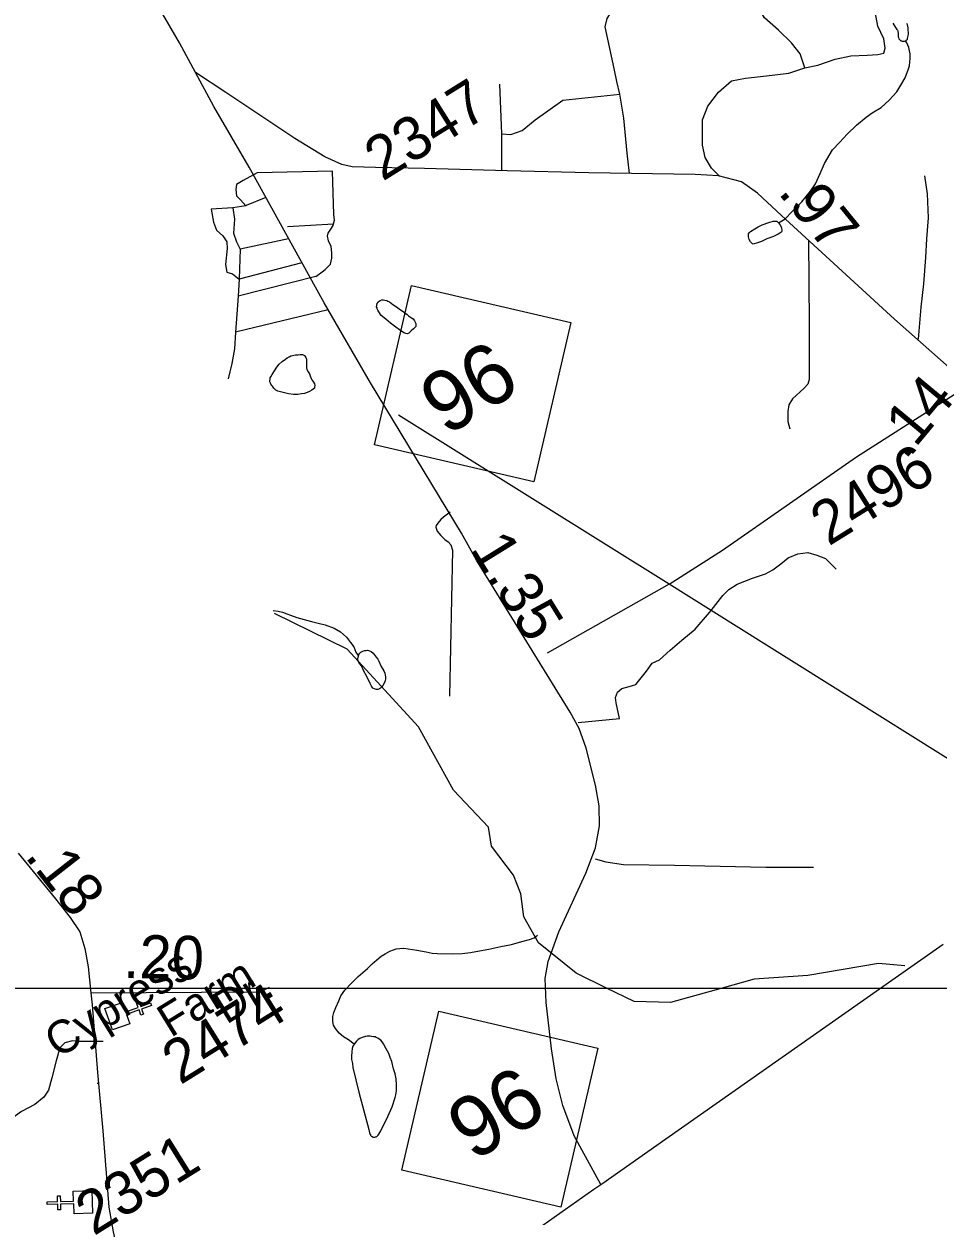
# Model space of a CAD drawing. Extents: x 2001466 to 31450019, y -30647475 to 847247.
# Drawn here: x 2204779 to 2210046, y 744293 to 751164 of the extents above; entities that cross this region are included whole.
import ezdxf

# ---------------------------------------------------------------- set-up
doc = ezdxf.new("R2010")
doc.units = 0
for name, color, linetype in [('Exist Boundary Political CountyLine', 7, 'Continuous'), ('Exist Cultural Church CELL', 7, 'Continuous'), ('Exist Hydrographic Creek Single Shore', 7, 'Continuous'), ('Exist Hydrographic Misc Water Feature', 7, 'Continuous'), ('Exist Road Non-System Type 51', 7, 'Continuous'), ('Exist Road Non-System Type 51 Label', 7, 'Continuous'), ('Exist Road Primary NC Attributed', 7, 'Continuous'), ('Exist Road Primary NC Service Mileage Hundredths English Label', 7, 'Continuous'), ('Exist Road Primary NC Shield CELL', 7, 'Continuous'), ('Exist Road Primary NC Shield Number Label', 7, 'Continuous'), ('Exist Road Secondary Mileage Hundredths English Label', 7, 'Continuous'), ('Exist Road Secondary Type 51 Attributed', 7, 'Continuous'), ('Exist Road Secondary Type 51 Label', 7, 'Continuous'), ('Exist Road Secondary Type 51 Number Label', 7, 'Continuous'), ('Exist Utilities Electrical Transmission Line', 7, 'Continuous'), ('Map Preparation Inset Cut Line', 7, 'Continuous')]:
    doc.layers.add(name, color=color, linetype=linetype)

msp = doc.modelspace()

# ---------------------------------------------------------------- linework, layer by layer
at = {"layer": 'Exist Boundary Political CountyLine'}
msp.add_lwpolyline([(2207605.3, 744126.8), (2208063.6, 744447.8), (2208103.1, 744475.5), (2208113.8, 744483.1), (2208477.8, 744738), (2209797.9, 745665.9), (2210074.9, 745860.5)], dxfattribs=at)
at = {"layer": 'Exist Cultural Church CELL'}
for points in [[(2205346.5, 745524.9), (2205365.5, 745471.2), (2205437.3, 745496.4), (2205426.8, 745526.6), (2205441.8, 745531.9), (2205452.4, 745501.7), (2205509.2, 745521.6), (2205514.5, 745506.5), (2205457.7, 745486.6), (2205468.3, 745456.4), (2205453.2, 745451.1), (2205442.6, 745481.3), (2205370.8, 745456.1), (2205389.8, 745401.7), (2205289.3, 745366.4), (2205246.1, 745489.7)], [(2205068, 744307.2), (2205066.1, 744364.1), (2204990, 744361.8), (2204991, 744329.8), (2204975, 744329.3), (2204974, 744361.3), (2204913.9, 744359.5), (2204913.5, 744375.5), (2204973.6, 744377.3), (2204972.6, 744409.3), (2204988.6, 744409.8), (2204989.5, 744377.8), (2205065.6, 744380.1), (2205064, 744437.8), (2205170.4, 744441), (2205174.4, 744310.4)]]:
    msp.add_lwpolyline(points, close=True, dxfattribs=at)
at = {"layer": 'Exist Hydrographic Creek Single Shore'}
for points in [[(2207743.7, 745868.8), (2207659.8, 746018.1), (2207641.8, 746149.7), (2207599.8, 746258.8), (2207473.6, 746425.4), (2207455.8, 746534), (2207254.6, 746748.1), (2207052.7, 747113.1), (2206640.7, 747561), (2206222.8, 747766.4)], [(2208136.1, 745607.9), (2207961.7, 745693.7), (2207743.7, 745868.8)], [(2209855, 745735.1), (2209702.8, 745749.9), (2209294.7, 745679.5), (2208986.7, 745659.7), (2208801.3, 745607.9)], [(2208801.3, 745607.9), (2208504.6, 745525.2), (2208295.7, 745529.4), (2208136.1, 745607.9)]]:
    msp.add_lwpolyline(points, dxfattribs=at)
at = {"layer": 'Exist Hydrographic Misc Water Feature'}
for points in [[(2209785, 751167.7), (2209801, 751143.8), (2209809.2, 751132), (2209811.2, 751128), (2209813.5, 751124), (2209813.3, 751120), (2209815.3, 751110), (2209815.5, 751098.2), (2209815.5, 751090.1), (2209817.8, 751086.1), (2209819.9, 751078), (2209824, 751074.2), (2209827.8, 751069.9), (2209831.9, 751066.1), (2209835.8, 751066.3), (2209839.5, 751064.1), (2209845.5, 751064.1), (2209852, 751064.3), (2209857.8, 751066.3)], [(2209857.8, 751066.3), (2209861.7, 751068.5), (2209863.5, 751072.3), (2209869.3, 751076.3), (2209869.5, 751080.3), (2209873.6, 751094.3), (2209875.6, 751106.6), (2209875, 751116.3), (2209873, 751124.4), (2209873.2, 751140.2), (2209870.9, 751150.2), (2209868.9, 751158.3), (2209866.8, 751166.3)], [(2209127, 750017.7), (2209165.1, 750039.9), (2209204.9, 750082.2), (2209260.1, 750138.3), (2209311.7, 750200.7), (2209339.2, 750241.2), (2209367.1, 750301.1), (2209390.9, 750359.1), (2209438.2, 750437.6), (2209479.7, 750482), (2209521.3, 750528), (2209575, 750580.4), (2209630.8, 750626.7), (2209666.9, 750651.3), (2209718.6, 750681.6), (2209764.3, 750723.8), (2209807.5, 750772), (2209831.3, 750810.2), (2209857, 750852.2), (2209874.8, 750904.7), (2209880.5, 750922.4), (2209882.6, 750944.5), (2209884.2, 750964.5), (2209884.2, 750990.4), (2209881.8, 751008.6), (2209877.9, 751028.3), (2209865.6, 751054.5), (2209857.8, 751066.3)], [(2209127, 750017.7), (2209133.3, 750007.8), (2209141.3, 749993.6), (2209143.6, 749983.9), (2209145.4, 749977.6), (2209145.2, 749971.9), (2209143.4, 749965.7), (2209139.3, 749961.8), (2209133.5, 749957.8), (2209123.7, 749951.6), (2209097.9, 749939.3), (2209059.7, 749925.2), (2209027.7, 749908.9), (2209000.1, 749900.9), (2208985.7, 749896.6), (2208980, 749894.7), (2208975.9, 749896.5), (2208972, 749900.7), (2208966, 749908.5), (2208957.8, 749920.7), (2208955.8, 749928.7), (2208953.7, 749936.4), (2208953.7, 749946.5), (2208953.7, 749954.6), (2208957.6, 749960.5), (2208965.6, 749966.6), (2208989.4, 749982.9), (2209009.3, 749994.9), (2209033.1, 750005.1), (2209071.2, 750019.2), (2209095, 750027.4), (2209107.3, 750027.5), (2209113.2, 750027.5), (2209117.1, 750027.7), (2209123.3, 750021.5), (2209127, 750017.7)], [(2206949.3, 749516.6), (2206969.6, 749503), (2206987.7, 749488.9), (2206995.7, 749481.2), (2207012.1, 749469), (2207021.7, 749463.5), (2207030.1, 749453.3), (2207034, 749445.4), (2207038.1, 749437.5), (2207038.1, 749431.4), (2207037.9, 749423.3), (2207038.1, 749419.6), (2207024.2, 749407.1), (2207010.4, 749395.4), (2207002.2, 749387.3), (2206996.5, 749381.3), (2206992.8, 749379), (2206988.7, 749377.2), (2206980.5, 749378.9), (2206974.3, 749381), (2206968.8, 749383.1), (2206942.4, 749400.8), (2206922.1, 749416.9), (2206892.1, 749438.5), (2206864.2, 749462.1), (2206837.8, 749484), (2206824, 749503.9), (2206817.5, 749513.8), (2206815.4, 749521.8), (2206813.6, 749527.8), (2206811.5, 749533.8), (2206813.2, 749543.6), (2206815.4, 749551.8), (2206819.3, 749559.8), (2206825.3, 749565.7), (2206831.2, 749569.7), (2206841.3, 749573.9), (2206851.3, 749574), (2206859.1, 749572), (2206869.4, 749570), (2206875.1, 749566.4), (2206885.1, 749562.4), (2206905.4, 749546.4), (2206925.5, 749532.4), (2206949.3, 749516.6)], [(2206416, 749159.5), (2206424.2, 749147.3), (2206428.3, 749135.3), (2206434.4, 749119.4), (2206438.5, 749113.5), (2206444.5, 749105.3), (2206448.6, 749099.4), (2206452.9, 749089.4), (2206454.5, 749079.4), (2206452.9, 749071.6), (2206452.7, 749065.5), (2206446.5, 749059.5), (2206437.1, 749053.3), (2206425, 749045.3), (2206410.9, 749039.4), (2206395.1, 749033.2), (2206379.1, 749031.2), (2206356.9, 749028.9), (2206333.1, 749028.8), (2206303.2, 749032.5), (2206281.1, 749038.3), (2206257.1, 749044.3), (2206242.9, 749048.1), (2206231, 749053.9), (2206219.1, 749063.9), (2206210.9, 749075.7), (2206206.8, 749079.9), (2206202.7, 749087.9), (2206199, 749093.7), (2206197, 749101.7), (2206196.6, 749107.8), (2206198.4, 749115.6), (2206198.4, 749123.8), (2206202.5, 749129.6), (2206210.3, 749143.9), (2206222.2, 749164), (2206236, 749185.8), (2206250.1, 749202), (2206267.7, 749218), (2206285.8, 749232.3), (2206295.8, 749238.5), (2206307.7, 749244.4), (2206317.8, 749250.6), (2206327.4, 749252.8), (2206343.4, 749256.8), (2206359.6, 749256.8), (2206371.3, 749258.7), (2206383.8, 749258.9), (2206391.6, 749254.8), (2206395.5, 749253), (2206403.3, 749241.3), (2206405.7, 749237.3), (2206407.8, 749227.2), (2206408.2, 749201.2), (2206407.8, 749181.4), (2206410, 749171.3), (2206416, 749159.5)], [(2206215.6, 747782.6), (2206243.5, 747778.8), (2206269.8, 747772.8), (2206294, 747765), (2206315.5, 747756.9), (2206352, 747743.3), (2206394.3, 747731.6), (2206436.1, 747720.1), (2206474.4, 747710.2), (2206514, 747700.6), (2206566.5, 747680.9), (2206602.6, 747661.2), (2206638.7, 747629.4), (2206660.8, 747599.3), (2206679.1, 747573.5), (2206691, 747543.6), (2206707, 747519.7)], [(2206846.8, 747351), (2206838.8, 747340.8), (2206834.3, 747335), (2206828.6, 747331), (2206818.9, 747328.8), (2206808.7, 747328.7), (2206798.2, 747332.7), (2206790.4, 747336.4), (2206782.2, 747346.5), (2206774.4, 747362.3), (2206754.1, 747402.2), (2206737.7, 747433.9), (2206723.8, 747464.1), (2206709.6, 747483.6), (2206705.3, 747492), (2206703.5, 747504), (2206705.7, 747513.8), (2206707, 747519.7)], [(2206707, 747519.7), (2206709.2, 747529.9), (2206715.2, 747538), (2206721.3, 747543.9), (2206731.4, 747548.1), (2206740.8, 747551.9), (2206751, 747552), (2206759, 747554), (2206765.2, 747552.3), (2206770.7, 747550.2), (2206779.5, 747546.5), (2206791.4, 747536.6), (2206809.5, 747514.4), (2206817.7, 747502.6), (2206823.4, 747490.8), (2206838, 747461), (2206851.9, 747435), (2206857.9, 747423.1), (2206859.7, 747411.1), (2206862, 747399), (2206862.2, 747389.2), (2206860.3, 747378.9), (2206858.1, 747373.2), (2206846.8, 747351)], [(2206682.6, 745284.7), (2206648.5, 745310.1), (2206620.6, 745326.1), (2206594.6, 745347.9), (2206574.1, 745373.7), (2206563.8, 745393.9), (2206559.9, 745415.5), (2206559.9, 745443.5), (2206565.7, 745465.8), (2206577, 745495.7), (2206592.7, 745533.9), (2206605, 745563.7), (2206629, 745596.2), (2206664.3, 745634.3), (2206705.9, 745674.6), (2206757.8, 745720.8), (2206785.5, 745747), (2206813.4, 745771.1), (2206837.2, 745791.5), (2206861.2, 745805.7), (2206886.8, 745819.7), (2206908.9, 745827.7), (2206923.3, 745834), (2206944.8, 745836.1), (2206969, 745838.1), (2206993, 745834.5), (2207043, 745826.9), (2207096.8, 745817.2), (2207131.2, 745809.5), (2207160.9, 745807.5), (2207248.9, 745804.4), (2207303.2, 745806.7), (2207352.7, 745813), (2207404.7, 745821.4), (2207458.7, 745831.9), (2207526.5, 745846.4), (2207588.5, 745858.5), (2207648.1, 745875.1), (2207692.4, 745887.5), (2207718.3, 745897.4), (2207738.2, 745911.8)], [(2206682.6, 745284.7), (2206674.6, 745272.5), (2206671.1, 745258.4), (2206668.8, 745240.5), (2206667, 745214.4), (2206667.4, 745196.5), (2206671.5, 745172.3), (2206673.9, 745150.5), (2206709, 745006.9), (2206766, 744793.4), (2206770.3, 744773.3), (2206772, 744767.4), (2206774.2, 744763.4), (2206778.3, 744757.5), (2206780.8, 744753.5), (2206784.7, 744751.6), (2206790.4, 744747.5), (2206798.4, 744747.5), (2206804.8, 744749.4), (2206808.5, 744749.7), (2206812.8, 744751.5), (2206816.5, 744755.8), (2206819.9, 744759.7), (2206824.4, 744765.5), (2206836.1, 744785.6), (2206875.5, 744868.1), (2206900.9, 744922.3), (2206919, 744976.4), (2206922.5, 744992.5), (2206926.4, 745016.2), (2206926.4, 745048.3), (2206923.7, 745084.4), (2206917.7, 745114.1), (2206909.5, 745142.1), (2206899.5, 745184.1), (2206889, 745208), (2206880.8, 745230), (2206866.9, 745258.1), (2206850.7, 745285.6), (2206842.5, 745297.8), (2206834.7, 745307.5), (2206826.3, 745313.7), (2206818.3, 745319.3), (2206808.5, 745323.3), (2206802.3, 745327.4), (2206792.5, 745327.3), (2206782.2, 745329.3), (2206774.4, 745331.2), (2206764.6, 745331.1), (2206756.6, 745331.1), (2206746.5, 745329), (2206728.5, 745322.7), (2206714.7, 745316.8), (2206704.3, 745310.6), (2206694.7, 745300.7), (2206682.6, 745284.7)]]:
    msp.add_lwpolyline(points, dxfattribs=at)
at = {"layer": 'Exist Road Non-System Type 51'}
for p, q in [((2207531.7, 750531), (2207520.3, 750815.9)), ((2207531.7, 750322.2), (2207531.7, 750531)), ((2206058.2, 750116.1), (2205983.8, 750103.1)), ((2206298.4, 749995.8), (2206563.8, 750012.1)), ((2206304.2, 749925.1), (2206026.1, 749866.1)), ((2206026.1, 749866.1), (2206018.6, 749692.3)), ((2206380.4, 749787.4), (2206018.6, 749692.3)), ((2206460.8, 749707.2), (2206014.6, 749594.4)), ((2206018.6, 749692.3), (2206014.6, 749594.4)), ((2206014.6, 749594.4), (2205998.3, 749386.7)), ((2206531.4, 749516.4), (2205998.3, 749386.7))]:
    msp.add_line(p, q, dxfattribs=at)
for points in [[(2208212.8, 750759.1), (2208195.9, 750831.1), (2208180.7, 750907), (2208127.6, 751146.3), (2208138.9, 751195.6), (2208165.5, 751237.4), (2208199.7, 751237.4), (2208271.8, 751233.6), (2208336.3, 751245), (2208393.2, 751298.2), (2208480.5, 751408.3), (2208556.5, 751491.9), (2208590.6, 751529.8), (2208598.2, 751628.6), (2208602, 751742.5), (2208613.4, 751799.5), (2208643.8, 751833.6), (2208719.7, 751890.6), (2208772.8, 751909.6), (2208829.7, 751921), (2208920.8, 751985.6)], [(2209277.6, 750910.8), (2209353.5, 750926), (2209452.2, 750960.2), (2209543.3, 750979.2), (2209638.2, 750983), (2209698.9, 750986.8), (2209733.1, 750994.4), (2209740.7, 751024.7), (2209733.1, 751077.9), (2209698.9, 751150.1), (2209683.7, 751233.6), (2209645.8, 751427.3), (2209626.8, 751533.6), (2209619.2, 751621)], [(2209277.6, 750910.8), (2209251, 750990.6), (2209201.7, 751055.1), (2209125.8, 751127.3), (2209046.1, 751199.4), (2209000.5, 751275.4), (2208977.8, 751362.7), (2208985.4, 751472.9)], [(2208786.6, 750287), (2208740.3, 750331.9), (2208703.9, 750392.9), (2208687.8, 750464.7), (2208687.8, 750526), (2208689.5, 750611.6), (2208719.7, 750690.6), (2208780.4, 750770.3), (2208856.3, 750834.9), (2208936, 750850.1), (2209057.5, 750865.2), (2209186.5, 750880.4), (2209277.6, 750910.8)], [(2207531.7, 750531), (2207584.8, 750527.3), (2207649.3, 750550), (2207725.2, 750610.8), (2207884.6, 750724.7), (2208212.8, 750759.1)], [(2208268.4, 750301.8), (2208255.4, 750418.8), (2208234.9, 750620.2), (2208212.8, 750759.1)], [(2206123.2, 750306), (2206043.2, 750261.4), (2206003.6, 750238.3), (2206000.3, 750208.7), (2206003.6, 750172.4), (2206026.7, 750149.3), (2206058.2, 750116.1)], [(2206563.8, 750012.1), (2206569.5, 750032.9), (2206564.1, 750065), (2206557.3, 750315.1), (2206123.2, 750306)], [(2209968, 750289.1), (2209983.9, 750184.8), (2209989, 750046.7), (2209978.5, 749925), (2209974.3, 749817.1), (2209961.2, 749665.4), (2209946.4, 749531.7), (2209930.5, 749346.2)], [(2205983.8, 750103.1), (2205858.6, 750096.6), (2205871.8, 750020.7), (2205888.3, 749974.5), (2205924.5, 749941.6), (2205947.6, 749908.6), (2205950.9, 749869), (2205941, 749776.7), (2205947.6, 749733.8), (2205980.6, 749723.9), (2206018.6, 749692.3)], [(2205983.8, 750103.1), (2205991.7, 750038.8), (2205987.1, 749958.1), (2206003.6, 749908.6), (2206026.1, 749866.1)], [(2206172.7, 750162.8), (2206059.6, 750116.3), (2206058.2, 750116.1)], [(2206460.8, 749707.2), (2206497.3, 749734.4), (2206515.6, 749748.1), (2206546.2, 749779.4), (2206552.9, 749813.3), (2206553.6, 749845.3), (2206550.3, 749881.3), (2206535, 749913.6), (2206527.5, 749939.8), (2206531.9, 749957.7), (2206548.4, 749981.3), (2206560.8, 750001.1), (2206563.8, 750012.1)], [(2209300.1, 749916.8), (2209303.7, 749434.5), (2209302.7, 749114.5), (2209295.1, 749088), (2209274.2, 749065.2), (2209207.8, 749002.5), (2209186.9, 748968.3), (2209181.2, 748930.4), (2209181.2, 748873.4), (2209192.6, 748829.7)], [(2205998.3, 749386.7), (2205992.3, 749290.9), (2205976.6, 749207.2), (2205956.8, 749117.6)], [(2207234.7, 748349.6), (2207196.1, 748320.4), (2207181.9, 748308.6), (2207163.4, 748287), (2207155.2, 748273.2), (2207153, 748263.3), (2207160.5, 748241.1), (2207182, 748214.7), (2207203.5, 748192.2), (2207223.2, 748179.8), (2207238.9, 748161.5), (2207248.2, 748131.3), (2207230.9, 747289.8)], [(2208738.1, 747782.6), (2208805.5, 747870.3), (2208839.7, 747904.5), (2208889, 747934.9), (2208976.3, 747969.1), (2209052.3, 747995.6), (2209094, 748018.4), (2209139.6, 748052.6), (2209181.3, 748086.8), (2209238.2, 748109.6), (2209295.2, 748117.2), (2209348.3, 748102), (2209397.7, 748083), (2209458.4, 748022.2)], [(2207973.2, 747137.5), (2208209.6, 747160.1), (2208190.7, 747251.3), (2208186.9, 747281.7), (2208198.3, 747312.1), (2208224.8, 747334.8), (2208266.6, 747346.2), (2208304.5, 747357.6), (2208365.3, 747433.6), (2208399.4, 747479.2), (2208441.2, 747498.1), (2208501.9, 747555.1), (2208570.2, 747612.1), (2208646.1, 747676.6), (2208729.6, 747771.6), (2208738.1, 747782.6)], [(2208070.3, 746351.8), (2208131.8, 746334.2), (2208234.3, 746319), (2208526.6, 746315.2), (2209054.2, 746303.8), (2209327.4, 746303.8)], [(2205236.8, 745300.2), (2205092.5, 745300.1), (2205058.6, 745302.8), (2205014.3, 745291.7), (2204985.7, 745262.3), (2204964.2, 745188.7), (2204940.2, 745091.2), (2204920.8, 745019.7), (2204893.9, 744978.2), (2204843.1, 744937.3), (2204766.3, 744896.8), (2204689.1, 744840.4), (2204632.1, 744791.6), (2204565.2, 744743), (2204502.5, 744712.3), (2204401.5, 744660.4), (2204356.9, 744629.3), (2204320.2, 744596.1), (2204287.2, 744548.7), (2204250.6, 744515.5), (2204195.7, 744474.6), (2204116.7, 744426.3), (2204063.9, 744382.1)]]:
    msp.add_lwpolyline(points, dxfattribs=at)
at = {"layer": 'Exist Road Non-System Type 51 Label'}
msp.add_line((2205201.1, 745058.8), (2205204.4, 745058.9), dxfattribs=at)
at = {"layer": 'Exist Road Primary NC Attributed'}
for points in [[(2205767.9, 750883), (2205676.3, 751054.8), (2205566.5, 751243.3), (2205434.1, 751502.9), (2205238.9, 751861.1), (2205150, 752049.5), (2205122.8, 752097.7), (2205020.8, 752254.8)], [(2208103.1, 744475.5), (2207949.1, 744756.3), (2207884.2, 744930.1), (2207846.5, 745085.1), (2207819.3, 745256.8), (2207789, 745524.9), (2207782.7, 745663.1), (2207799.4, 745761.5), (2207860.1, 745931.2), (2208016.1, 746270.4), (2208072.6, 746415), (2208095.6, 746542.7), (2208093.5, 746657.9), (2208072.6, 746777.3), (2208019.2, 746990.9), (2207977.3, 747104), (2207927.1, 747198.2), (2207386.1, 748073.6), (2207300.3, 748228.6), (2206776.1, 749095.6), (2206508.2, 749556.3), (2206076.1, 750337.5), (2205873.1, 750687.2), (2205767.9, 750883)]]:
    msp.add_lwpolyline(points, dxfattribs=at)
at = {"layer": 'Exist Road Primary NC Shield CELL'}
for points in [[(2206798.9, 748737.9), (2207012.1, 749655.3), (2207929.5, 749442.2), (2207716.3, 748524.7)], [(2206955.8, 744557.8), (2207169, 745475.2), (2208086.4, 745262), (2207873.2, 744344.6)]]:
    msp.add_lwpolyline(points, close=True, dxfattribs=at)
at = {"layer": 'Exist Road Secondary Type 51 Attributed'}
for points in [[(2210278.2, 749039.6), (2210143.1, 749155.3), (2209795.7, 749463.1), (2209143.8, 750060), (2209005.7, 750187.8), (2208913.6, 750252.7), (2208781.7, 750288.3), (2208645.7, 750296.7), (2208033.6, 750305), (2207562.7, 750317.6), (2207086.6, 750330.2), (2206805.1, 750335.4), (2206670.1, 750340.6), (2206610.5, 750353.2), (2206513.7, 750398.2), (2206340, 750502.9), (2205942.4, 750768.9), (2205767.9, 750883)], [(2204745.4, 746384.7), (2204961.5, 746121.9), (2205045.2, 746014.8), (2205100.8, 745930.7), (2205130.9, 745835.5), (2205149.2, 745729.1), (2205165.6, 745580.3)], [(2205165.6, 745580.3), (2206120.7, 745586.5), (2206140.5, 745591.1), (2206158.7, 745595.7), (2206193.8, 745612.4)], [(2205165.6, 745580.3), (2205173.3, 745511.3), (2205204.1, 745120.7), (2205233.4, 744785.6), (2205268.5, 744344.8), (2205293.6, 744202.4), (2205383.6, 743785.6), (2205455.8, 743530.1), (2205543.7, 743314.4), (2205667.2, 743084), (2205800.4, 742874.8)]]:
    msp.add_lwpolyline(points, dxfattribs=at)
at = {"layer": 'Exist Utilities Electrical Transmission Line'}
for p, q in [((2208496, 747935.8), (2206938.3, 748909.5)), ((2208496, 747935.8), (2207793.9, 747538.2)), ((2208738.1, 747782.6), (2208496, 747935.8))]:
    msp.add_line(p, q, dxfattribs=at)
for points in [[(2208496, 747935.8), (2208803.9, 748131.4), (2209576.8, 748669.4), (2210228.3, 749086)], [(2210897.5, 746439), (2210872.9, 746446.1), (2208738.1, 747782.6)]]:
    msp.add_lwpolyline(points, dxfattribs=at)
at = {"layer": 'Map Preparation Inset Cut Line'}
for p, q in [((2202091.1, 745607.9), (2205205.2, 745607.9)), ((2205205.2, 745607.9), (2207796.6, 745607.9)), ((2207796.6, 745607.9), (2208136.1, 745607.9)), ((2208136.1, 745607.9), (2208801.3, 745607.9)), ((2208801.3, 745607.9), (2209730.1, 745607.9))]:
    msp.add_line(p, q, dxfattribs=at)
msp.add_lwpolyline([(2209730.1, 745607.9), (2211302.1, 745607.9), (2211302.1, 746701.8)], dxfattribs=at)

# ---------------------------------------------------------------- texts
at = {"layer": 'Exist Road Primary NC Service Mileage Hundredths English Label'}
msp.add_text('1.35', height=250, rotation=301.71539, dxfattribs=at).set_placement((2207345.7, 748139))
at = {"layer": 'Exist Road Primary NC Shield Number Label'}
for p in [(2207211.4, 748783.5), (2207368.4, 744603.4)]:
    msp.add_text('96', height=350, rotation=31.91803, dxfattribs=at).set_placement(p)
at = {"layer": 'Exist Road Secondary Mileage Hundredths English Label'}
for s, rotation, p in [('.97', 309.17025, (2209119.4, 750190.7)), ('.14', 50.24174, (2209855.6, 748646.7)), ('.18', 308.00448, (2204779.9, 746366.2)), ('.20', 358.80785, (2205349.7, 745665.8))]:
    msp.add_text(s, height=250, rotation=rotation, dxfattribs=at).set_placement(p)
at = {"layer": 'Exist Road Secondary Type 51 Label'}
for s, p in [('Cypress ', (2204975.7, 745199.1)), ('Farm', (2205625.1, 745319.2)), ('Dr.', (2205945.7, 745395.1))]:
    msp.add_text(s, height=190, rotation=31.65519, dxfattribs=at).set_placement(p)
at = {"layer": 'Exist Road Secondary Type 51 Number Label'}
for s, p in [('2347', (2206845.1, 750253.5)), ('2496', (2209415.2, 748151.3)), ('2474', (2205679.8, 745046.6)), ('2351', (2205181.4, 744176.3))]:
    msp.add_text(s, height=250, rotation=31.91803, dxfattribs=at).set_placement(p)

doc.saveas('drawing.dxf')
